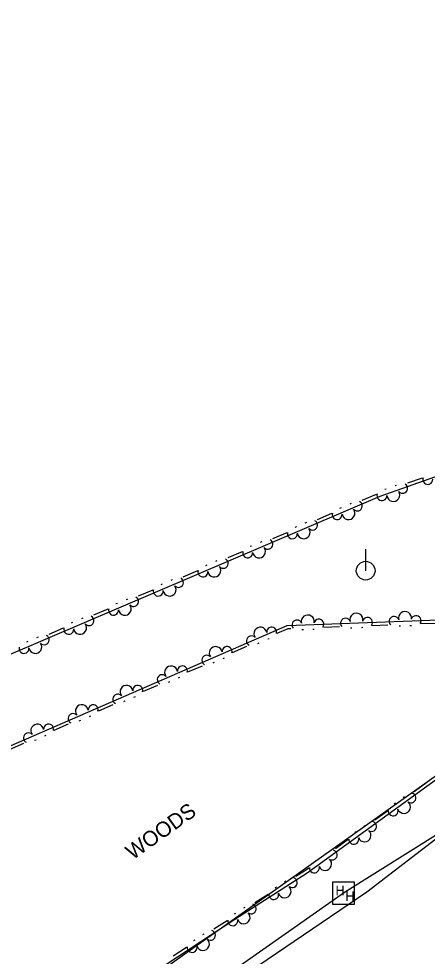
# Model space of a CAD drawing. Extents: x 1577032 to 1581865, y 611492 to 615011.
# Drawn here: x 1578654.5 to 1578761.3, y 612619.6 to 612864.7 of the extents above; entities that cross this region are included whole.
import ezdxf

# ---------------------------------------------------------------- set-up
doc = ezdxf.new("R2010")
doc.units = 0
for name, color, linetype in [('Exist Right of Way Line', 7, 'Continuous'), ('Exist Utilities Power Pole CELL', 7, 'Continuous'), ('Exist Utilities Telephone Hand Hole CELL', 7, 'Continuous'), ('Exist Utilities Telephone UG FO SUE LOS B', 7, 'Continuous'), ('Exist Utilities Water UG Line SUE LOS B', 7, 'Continuous'), ('Exist Vegetation Woods Line Text', 7, 'Continuous'), ('Old_Level_11', 7, 'Continuous')]:
    doc.layers.add(name, color=color, linetype=linetype)

msp = doc.modelspace()

# ---------------------------------------------------------------- linework, layer by layer
at = {"layer": 'Exist Right of Way Line'}
msp.add_lwpolyline([(1578124.38, 612213.06), (1579205.66, 612980.92)], dxfattribs=at)
at = {"layer": 'Exist Utilities Power Pole CELL'}
for q in [(1578745.2, 612726.06), (1578745.2, 612720.44)]:
    msp.add_line((1578745.2, 612720.44), q, dxfattribs=at)
msp.add_circle((1578745.2, 612720.44), 2.45, dxfattribs=at)
at = {"layer": 'Exist Utilities Telephone Hand Hole CELL'}
for p, q in [((1578736.53, 612639.02), (1578736.53, 612633.29)), ((1578742.25, 612639.02), (1578736.53, 612639.02)), ((1578742.25, 612633.29), (1578742.25, 612639.02)), ((1578739.39, 612636.16), (1578739.39, 612636.16)), ((1578736.53, 612633.29), (1578742.25, 612633.29))]:
    msp.add_line(p, q, dxfattribs=at)
at = {"layer": 'Exist Utilities Telephone UG FO SUE LOS B'}
msp.add_lwpolyline([(1578195.73, 612250.34), (1578241.59, 612286.54), (1578291.86, 612328.33), (1578346.38, 612374.92), (1578396.97, 612410.49), (1578454.86, 612448.05), (1578513.8, 612486.88), (1578570.79, 612520.18), (1578660.13, 612580.57), (1578739.65, 612636.41), (1578799.35, 612673.77), (1578835.75, 612699.17), (1578865.6, 612719.98), (1578923.89, 612761.36), (1578953.65, 612786.53), (1578992.35, 612823.36), (1579016.04, 612847.4), (1579030.15, 612863.93), (1579038.32, 612877.78)], dxfattribs=at)
at = {"layer": 'Exist Utilities Water UG Line SUE LOS B'}
for p, q in [((1578745.5, 612636.5), (1578797.66, 612676.66)), ((1578661.05, 612579.23), (1578745.5, 612636.5))]:
    msp.add_line(p, q, dxfattribs=at)
at = {"layer": 'Old_Level_11'}
for points in [[(1578854.39, 612741.35), (1578805.77, 612755.29), (1578776.22, 612749.53), (1578748.88, 612739.86), (1578397.75, 612589.78), (1578202.57, 612520.47)], [(1578760, 612744.66), (1578756.13, 612743.29)], [(1578750.58, 612741.76), (1578750.19, 612741.63)], [(1578753.29, 612742.72), (1578752.9, 612742.58)], [(1578747.98, 612740.36), (1578744.21, 612738.75)], [(1578738.77, 612736.87), (1578738.39, 612736.71)], [(1578741.4, 612738), (1578741.03, 612737.84)], [(1578736.29, 612735.37), (1578732.52, 612733.75)], [(1578727.08, 612731.87), (1578726.7, 612731.71)], [(1578729.71, 612733), (1578729.34, 612732.84)], [(1578724.6, 612730.37), (1578720.82, 612728.76)], [(1578715.39, 612726.88), (1578715.01, 612726.72)], [(1578718.02, 612728.01), (1578717.65, 612727.84)], [(1578712.91, 612725.37), (1578709.14, 612723.76)], [(1578703.7, 612721.88), (1578703.32, 612721.72)], [(1578706.33, 612723.01), (1578705.96, 612722.85)], [(1578701.22, 612720.38), (1578697.44, 612718.76)], [(1578692, 612716.88), (1578691.63, 612716.72)], [(1578694.65, 612718.01), (1578694.27, 612717.85)], [(1578689.53, 612715.38), (1578685.75, 612713.77)], [(1578680.31, 612711.89), (1578679.93, 612711.73)], [(1578682.95, 612713.02), (1578682.58, 612712.86)], [(1578219.14, 612501.33), (1578402.75, 612566.18), (1578724.72, 612706.14), (1578817.97, 612709.56)], [(1578817.97, 612709.56), (1578809.14, 612701.87), (1578766.25, 612667.71), (1578729.93, 612641.39), (1578711, 612629.29), (1578666.02, 612599.72), (1578626.26, 612569.19), (1578597.37, 612539.75), (1578558.5, 612501.79), (1578537.75, 612486.32), (1578502.24, 612463.66), (1578465.91, 612440.49), (1578423.86, 612413.78), (1578371.1, 612378.99), (1578339.9, 612361.7)], [(1578677.84, 612710.38), (1578674.06, 612708.77)], [(1578668.62, 612706.89), (1578668.25, 612706.73)], [(1578671.26, 612708.02), (1578670.89, 612707.86)], [(1578759.63, 612706.6), (1578763.73, 612706.75)], [(1578666.14, 612705.39), (1578662.37, 612703.77)], [(1578722.08, 612704.11), (1578724.9, 612705.33), (1578725.62, 612705.36)], [(1578728.5, 612705.05), (1578728.91, 612705.07)], [(1578731.37, 612705.16), (1578731.78, 612705.17)], [(1578734.22, 612705.67), (1578738.32, 612705.82)], [(1578741.21, 612705.52), (1578741.62, 612705.53)], [(1578744.07, 612705.62), (1578744.48, 612705.64)], [(1578746.93, 612706.14), (1578751.03, 612706.29)], [(1578753.91, 612705.98), (1578754.32, 612706)], [(1578756.78, 612706.09), (1578757.19, 612706.1)], [(1578656.93, 612701.9), (1578656.56, 612701.73)], [(1578659.57, 612703.02), (1578659.19, 612702.86)], [(1578719.61, 612702.59), (1578719.99, 612702.75)], [(1578710.42, 612699.04), (1578714.18, 612700.67)], [(1578716.98, 612701.44), (1578717.36, 612701.6)], [(1578707.95, 612697.52), (1578708.33, 612697.68)], [(1578698.76, 612693.97), (1578702.53, 612695.6)], [(1578705.32, 612696.37), (1578705.7, 612696.54)], [(1578696.29, 612692.45), (1578696.67, 612692.61)], [(1578687.1, 612688.9), (1578690.87, 612690.54)], [(1578693.66, 612691.3), (1578694.04, 612691.47)], [(1578684.64, 612687.38), (1578685.01, 612687.54)], [(1578675.45, 612683.83), (1578679.21, 612685.47)], [(1578682, 612686.24), (1578682.38, 612686.4)], [(1578672.98, 612682.31), (1578673.35, 612682.47)], [(1578663.79, 612678.76), (1578667.55, 612680.4)], [(1578670.34, 612681.17), (1578670.72, 612681.33)], [(1578661.32, 612677.24), (1578661.69, 612677.41)], [(1578652.13, 612673.7), (1578655.89, 612675.33)], [(1578658.68, 612676.1), (1578659.06, 612676.26)], [(1578761.2, 612665.07), (1578757.88, 612662.66)], [(1578755.31, 612661.31), (1578754.98, 612661.07)], [(1578752.99, 612659.62), (1578752.66, 612659.38)], [(1578750.91, 612657.61), (1578747.59, 612655.2)], [(1578745.02, 612653.84), (1578744.69, 612653.6)], [(1578742.7, 612652.16), (1578742.36, 612651.92)], [(1578740.61, 612650.14), (1578737.29, 612647.74)], [(1578734.73, 612646.38), (1578734.4, 612646.14)], [(1578732.4, 612644.7), (1578732.07, 612644.46)], [(1578730.32, 612642.68), (1578729.47, 612642.07), (1578726.94, 612640.45)], [(1578724.3, 612639.25), (1578723.95, 612639.02)], [(1578719.68, 612635.81), (1578716.23, 612633.6)], [(1578721.88, 612637.7), (1578721.53, 612637.48)], [(1578711.17, 612630.85), (1578710.83, 612630.63)], [(1578713.59, 612632.4), (1578713.24, 612632.18)], [(1578708.98, 612628.93), (1578705.55, 612626.68)], [(1578700.53, 612623.87), (1578700.18, 612623.65)], [(1578702.92, 612625.45), (1578702.58, 612625.22)], [(1578698.35, 612621.95), (1578694.92, 612619.7)]]:
    msp.add_lwpolyline(points, dxfattribs=at)
for centre, radius, start, end in [((1578761.43, 612744.3), 1.3, 160.2538, 1.0504), ((1578752.42, 612740.24), 1.69, 185.4491, 33.5216), ((1578754.86, 612741.97), 1.3, 217.9203, 58.7169), ((1578743.02, 612737.35), 1.3, 221.5777, 62.3743), ((1578749.44, 612740.06), 1.3, 160.2538, 1.0504), ((1578740.7, 612735.47), 1.69, 189.1065, 37.179), ((1578737.74, 612735.1), 1.3, 163.9112, 4.7078), ((1578729.01, 612730.47), 1.69, 189.1065, 37.179), ((1578731.33, 612732.36), 1.3, 221.5777, 62.3743), ((1578726.05, 612730.1), 1.3, 163.9112, 4.7078), ((1578717.32, 612725.48), 1.69, 189.1065, 37.179), ((1578719.64, 612727.36), 1.3, 221.5777, 62.3743), ((1578714.36, 612725.1), 1.3, 163.9112, 4.7078), ((1578705.63, 612720.48), 1.69, 189.1065, 37.179), ((1578707.95, 612722.36), 1.3, 221.5777, 62.3743), ((1578702.67, 612720.11), 1.3, 163.9112, 4.7078), ((1578693.94, 612715.48), 1.69, 189.1065, 37.179), ((1578696.26, 612717.37), 1.3, 221.5777, 62.3743), ((1578690.98, 612715.11), 1.3, 163.9112, 4.7078), ((1578684.57, 612712.37), 1.3, 221.5777, 62.3743), ((1578679.29, 612710.11), 1.3, 163.9112, 4.7078), ((1578682.25, 612710.49), 1.69, 189.1065, 37.179), ((1578742.77, 612707.63), 1.69, 348.0603, 196.1328), ((1578755.48, 612708.09), 1.69, 348.0603, 196.1328), ((1578672.88, 612707.37), 1.3, 221.5777, 62.3743), ((1578727.23, 612706.24), 1.3, 20.5315, 221.3281), ((1578730.07, 612707.16), 1.69, 348.0603, 196.1328), ((1578732.96, 612706.45), 1.3, 322.865, 163.6616), ((1578739.93, 612706.7), 1.3, 20.5315, 221.3281), ((1578745.67, 612706.91), 1.3, 322.865, 163.6616), ((1578752.64, 612707.17), 1.3, 20.5315, 221.3281), ((1578758.37, 612707.38), 1.3, 322.865, 163.6616), ((1578667.6, 612705.12), 1.3, 163.9112, 4.7078), ((1578670.56, 612705.49), 1.69, 189.1065, 37.179), ((1578717.67, 612703.98), 1.69, 9.4589, 217.5314), ((1578720.63, 612704.37), 1.3, 344.2636, 185.0602), ((1578661.19, 612702.38), 1.3, 221.5777, 62.3743), ((1578715.36, 612702.08), 1.3, 41.9301, 242.7266), ((1578655.91, 612700.12), 1.3, 163.9112, 4.7078), ((1578658.87, 612700.49), 1.69, 189.1065, 37.179), ((1578706.01, 612698.91), 1.69, 9.4589, 217.5314), ((1578708.97, 612699.3), 1.3, 344.2636, 185.0602), ((1578703.7, 612697.01), 1.3, 41.9301, 242.7266), ((1578694.35, 612693.84), 1.69, 9.4589, 217.5314), ((1578697.31, 612694.23), 1.3, 344.2636, 185.0602), ((1578692.04, 612691.94), 1.3, 41.9301, 242.7266), ((1578682.69, 612688.77), 1.69, 9.4589, 217.5314), ((1578685.65, 612689.16), 1.3, 344.2636, 185.0602), ((1578680.38, 612686.87), 1.3, 41.9301, 242.7266), ((1578671.03, 612683.7), 1.69, 9.4589, 217.5314), ((1578673.99, 612684.09), 1.3, 344.2636, 185.0602), ((1578668.72, 612681.8), 1.3, 41.9301, 242.7266), ((1578659.37, 612678.63), 1.69, 9.4589, 217.5314), ((1578662.33, 612679.03), 1.3, 344.2636, 185.0602), ((1578657.07, 612676.74), 1.3, 41.9301, 242.7266), ((1578757.03, 612661.03), 1.3, 234.3765, 75.1731), ((1578752.38, 612657.66), 1.3, 176.71, 17.5066), ((1578755.19, 612658.68), 1.69, 201.9053, 49.9778), ((1578746.74, 612653.57), 1.3, 234.3765, 75.1731), ((1578742.09, 612650.2), 1.3, 176.71, 17.5066), ((1578744.9, 612651.22), 1.69, 201.9053, 49.9778), ((1578736.45, 612646.11), 1.3, 234.3765, 75.1731), ((1578731.8, 612642.74), 1.3, 176.71, 17.5066), ((1578734.6, 612643.76), 1.69, 201.9053, 49.9778), ((1578726, 612638.87), 1.3, 231.0245, 71.8211), ((1578721.16, 612635.78), 1.3, 173.3581, 14.1546), ((1578724.02, 612636.63), 1.69, 198.5533, 46.6258), ((1578715.29, 612632.02), 1.3, 231.0245, 71.8211), ((1578713.31, 612629.79), 1.69, 198.5533, 46.6258), ((1578710.45, 612628.93), 1.3, 174.0834, 14.88), ((1578704.63, 612625.1), 1.3, 231.7499, 72.5465), ((1578702.68, 612622.83), 1.69, 199.2787, 47.3512), ((1578699.83, 612621.94), 1.3, 174.0834, 14.88)]:
    msp.add_arc(centre, radius, start, end, dxfattribs=at)

# ---------------------------------------------------------------- texts
at = {"layer": 'Exist Utilities Telephone Hand Hole CELL'}
for p in [(1578737.3, 612635.56), (1578739.88, 612634.1)]:
    msp.add_text('H', height=2.5, dxfattribs=at).set_placement(p)
at = {"layer": 'Exist Vegetation Woods Line Text'}
msp.add_text('WOODS', height=4, rotation=35.38, dxfattribs=at).set_placement((1578684.31, 612644.7))

doc.saveas('drawing.dxf')
